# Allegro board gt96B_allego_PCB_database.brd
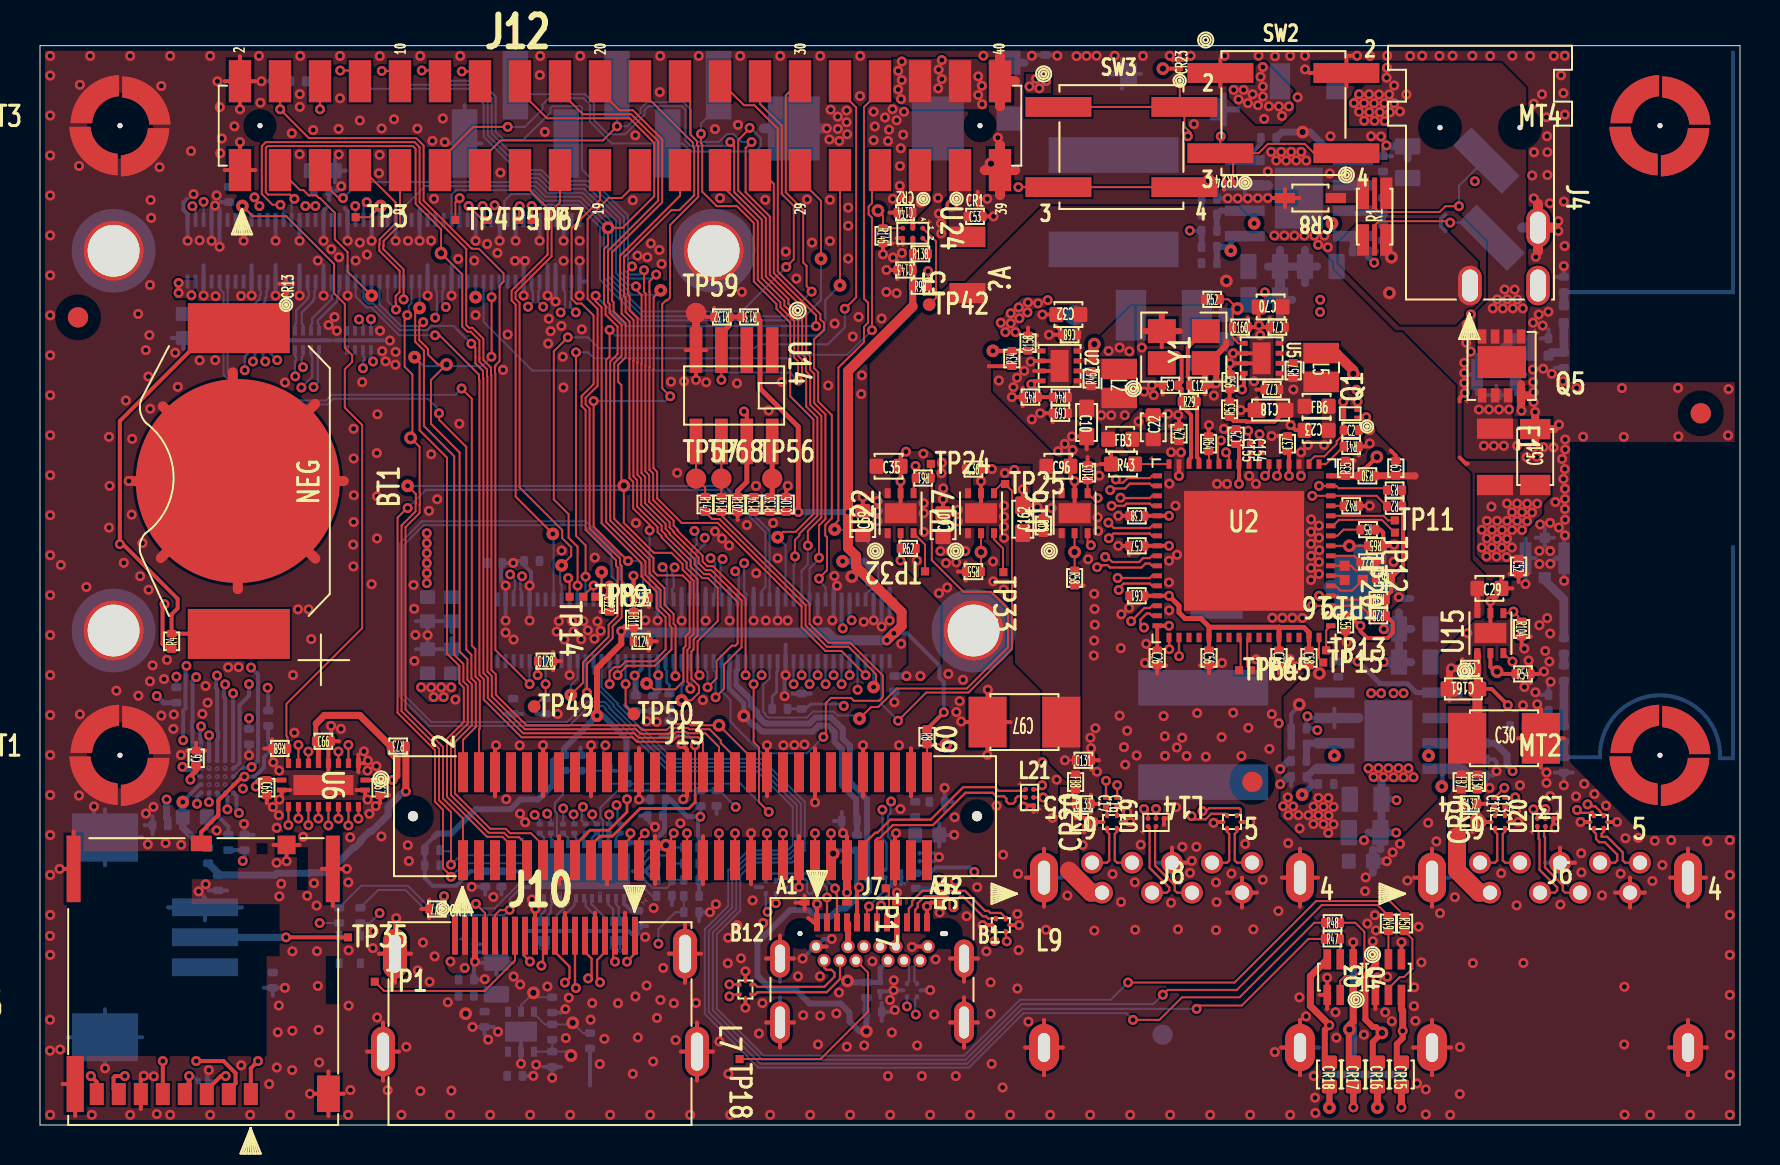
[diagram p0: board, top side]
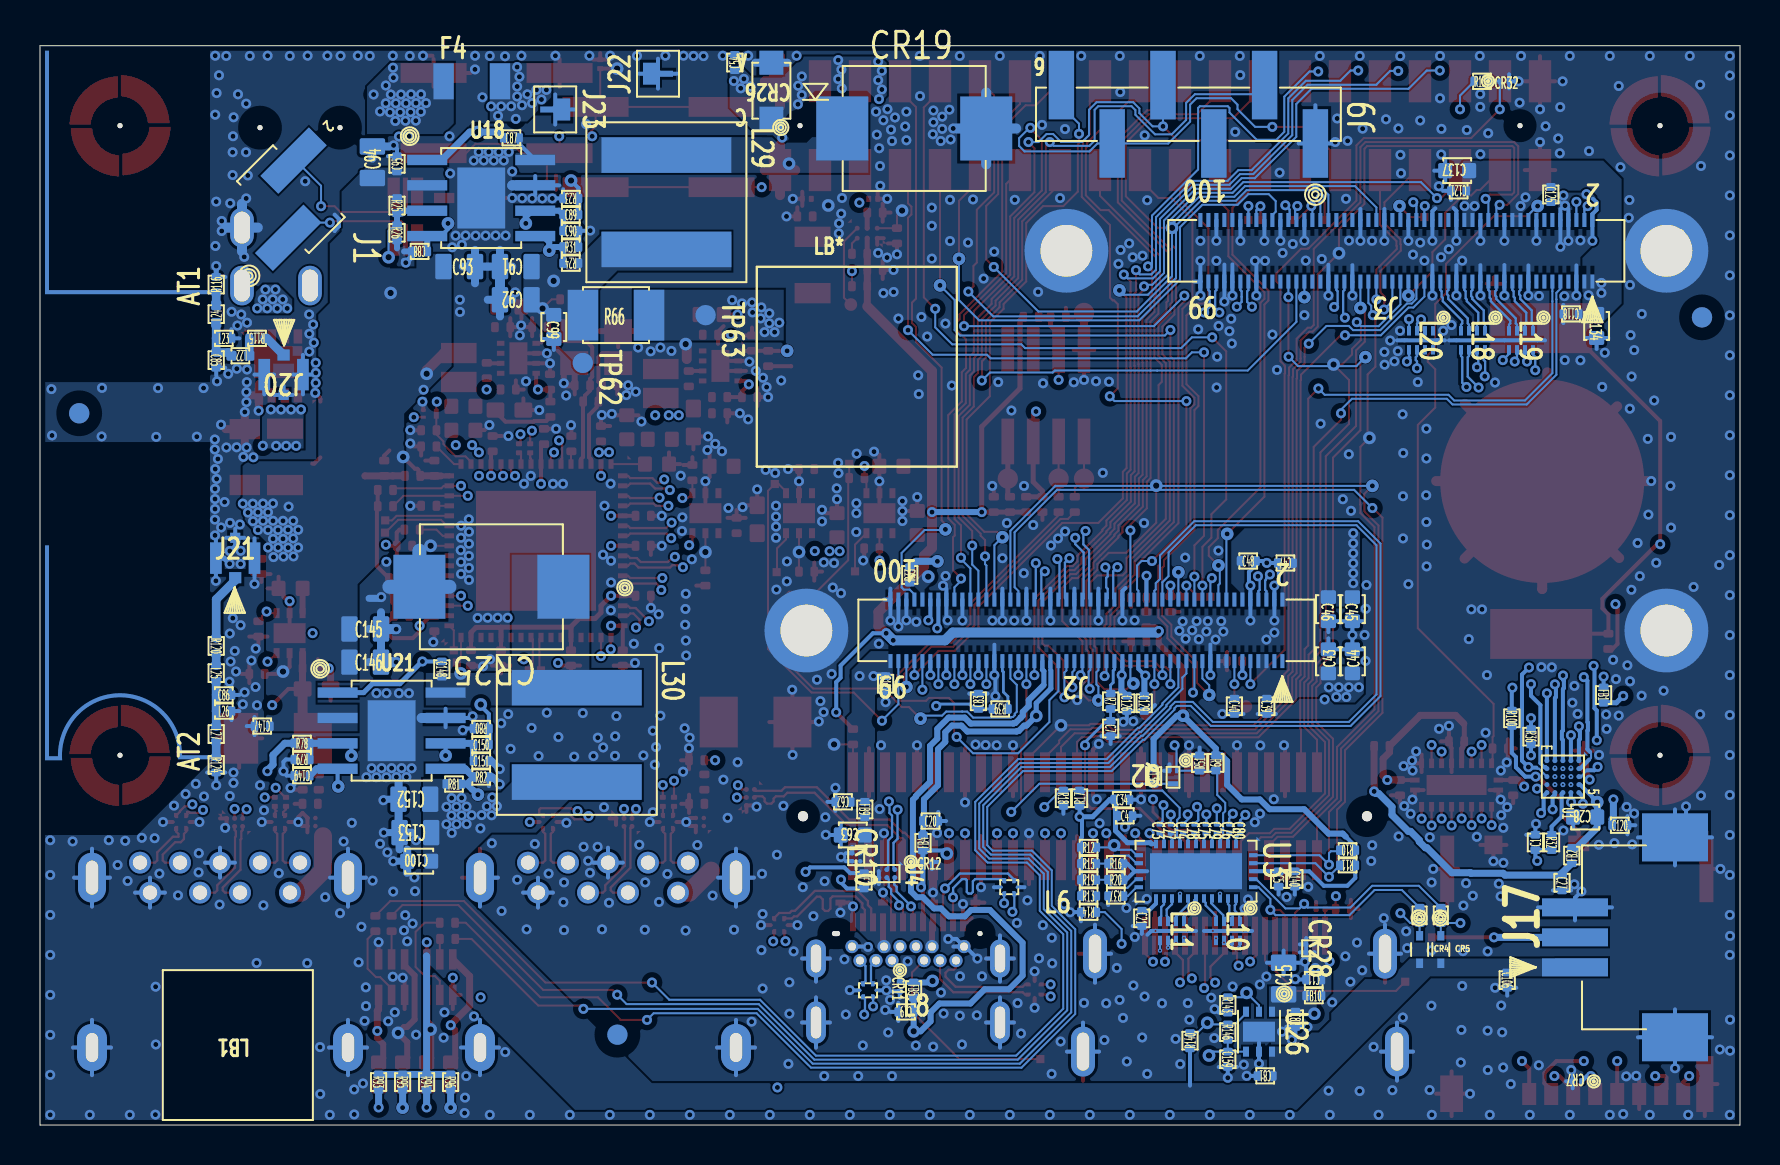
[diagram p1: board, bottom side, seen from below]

Outline 85 x 54 mm; copper layers: TOP, L2, L3, L4, L5, BOTTOM. Coordinates in mm from the lower left corner of the outline.
Outline path: 0,54 85,54 85,0 0,0 0,54

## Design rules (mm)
net group HUB1_USB2_1_D: nets HUB1_USB2_1_DN HUB1_USB2_1_DP
net group HUB1_USB3_1_RX_D: nets HUB1_USB3_1_RX_DN HUB1_USB3_1_RX_DP
net group HUB1_USB3_1_TX_D: nets HUB1_USB3_1_TX_DN HUB1_USB3_1_TX_DP
net group HUB1_USB3_1_TX_R_D: nets HUB1_USB3_1_TX_DN_C HUB1_USB3_1_TX_DP_C
net group HUB2_USB2_1_D: nets HUB2_USB2_1_DN HUB2_USB2_1_DP
net group HUB2_USB3_1_RX_D: nets HUB2_USB3_1_RX_DN HUB2_USB3_1_RX_DP
net group HUB2_USB3_1_TX_D: nets HUB2_USB3_1_TX_DN HUB2_USB3_1_TX_DP
net group HUB2_USB3_1_TX_R_D: nets HUB2_USB3_1_TX_DN_C HUB3_USB3_1_TX_DP_C
net group HUB3_USB2_1_CONN_D: nets HUB3_USB2_1_CONN_DN HUB3_USB2_1_CONN_DP
net group HUB3_USB2_1_D: nets HUB3_USB2_1_DN HUB3_USB2_1_DP
net group MDSI_A_DATA_3_CONN_D: nets MDSI_A_DATA_3_CONN_DN MDSI_A_DATA_3_CONN_DP
net group MDSI_A_DATA_3_D: nets MDSI_A_DATA_3_DN MDSI_A_DATA_3_DP
net group PCIE1_CLK_D: nets PCIE1_CLK_DN PCIE1_CLK_DP
net group USB2_0_D: nets USB2_0_DN USB2_0_DP
net group USB2_1_D: nets USB2_1_DN USB2_1_DP
net group USB3_0_MUX1_RX_D: nets USB3_0_MUX1_RX_DN USB3_0_MUX1_RX_DP
net group USB3_0_MUX1_TX_D: nets USB3_0_MUX1_TX_DN USB3_0_MUX1_TX_DP
net group USB3_0_MUX2_RX_D: nets USB3_0_MUX2_RX_DN USB3_0_MUX2_RX_DP
net group USB3_0_MUX2_TX_D: nets USB3_0_MUX2_TX_DN USB3_0_MUX2_TX_DP
net group USB3_0_RX_D: nets USB3_0_RX_DN USB3_0_RX_DP
net group USB3_0_TX_D: nets USB3_0_TX_DN USB3_0_TX_DP
net group USB3_1_RX_D: nets USB3_1_RX_DN USB3_1_RX_DP
net group USB3_1_RX_R: nets USB3_1_RX_DN_C USB3_1_RX_DP_C
net group USB3_1_TX_D: nets USB3_1_TX_DN USB3_1_TX_DP
net group USBA_1_USB2_1_D: nets USBA_1_USB2_1_DN USBA_1_USB2_1_DP
net group USBA_1_USB3_1_RX_D: nets USBA_1_USB3_1_RX_DN USBA_1_USB3_1_RX_DP
net group USBA_1_USB3_1_TX_D: nets USBA_1_USB3_1_TX_DN USBA_1_USB3_1_TX_DP
net group USBA_2_USB2_1_D: nets USBA_2_USB2_1_DN USBA_2_USB2_1_DP
net group USBA_2_USB3_1_RX_D: nets USBA_2_USB3_1_RX_DN USBA_2_USB3_1_RX_DP
net group USBA_2_USB3_1_TX_D: nets USBA_2_USB3_1_TX_DN USBA_2_USB3_1_TX_DP
net group USBC_USB2_0_D: nets USBC_USB2_0_DN USBC_USB2_0_DP
net group USBC_USB3_0_MUX1_RX_D: nets USBC_USB3_0_MUX1_RX_DN USBC_USB3_0_MUX1_RX_DP
net group USBC_USB3_0_MUX1_TX_D: nets USBC_USB3_0_MUX1_TX_DN USBC_USB3_0_MUX1_TX_DP
net group USBC_USB3_0_MUX2_RX_D: nets USBC_USB3_0_MUX2_RX_DN USBC_USB3_0_MUX2_RX_DP
net group USBC_USB3_0_MUX2_TX_D: nets USBC_USB3_0_MUX2_TX_DN USBC_USB3_0_MUX2_TX_DP
net group HDMI: nets HDMI_CLK_DN HDMI_CLK_DP HDMI_TX_0_DN HDMI_TX_0_DP HDMI_TX_1_DN HDMI_TX_1_DP HDMI_TX_2_DN HDMI_TX_2_DP
net group HDMI_C: nets HDMI_CLK_C_DN HDMI_CLK_C_DP HDMI_TX_0_C_DN HDMI_TX_0_C_DP HDMI_TX_1_C_DN HDMI_TX_1_C_DP HDMI_TX_2_C_DN HDMI_TX_2_C_DP
net group HDMI_CONN: nets HDMI_CLK_CONN_DN HDMI_CLK_CONN_DP HDMI_DAT0_CONN_DN HDMI_DAT0_CONN_DP HDMI_DAT1_CONN_DN HDMI_DAT1_CONN_DP HDMI_DAT2_CONN_DN HDMI_DAT2_CONN_DP
net group HDMI_OB: nets HDMI_OB_CLK_DN HDMI_OB_CLK_DP HDMI_OB_DAT0_DN HDMI_OB_DAT0_DP HDMI_OB_DAT1_DN HDMI_OB_DAT1_DP HDMI_OB_DAT2_DN HDMI_OB_DAT2_DP
net group MDSI_A: nets MDSI_A_CLK_DN MDSI_A_CLK_DP MDSI_A_DATA_0_DN MDSI_A_DATA_0_DP MDSI_A_DATA_1_DN MDSI_A_DATA_1_DP MDSI_A_DATA_2_DN MDSI_A_DATA_2_DP
net group MDSI_A_CONN: nets MDSI_A_CLK_CONN_DN MDSI_A_CLK_CONN_DP MDSI_A_DATA_0_CONN_DN MDSI_A_DATA_0_CONN_DP MDSI_A_DATA_1_CONN_DN MDSI_A_DATA_1_CONN_DP MDSI_A_DATA_2_CONN_DN MDSI_A_DATA_2_CONN_DP
net group SD_CARD: nets +V1P8V_MICROSD +V3P3V_MICROSD +VLDO_SDCARD
net group SDCARD: nets SDCARD_CD_N SDCARD_CD_N_CONN SDCARD_CLK SDCARD_CLK_CONN SDCARD_CLK_CONN_R SDCARD_CMD SDCARD_CMD_CONN SDCARD_D0 SDCARD_D0_CONN SDCARD_D1 SDCARD_D1_CONN SDCARD_D2 SDCARD_D2_CONN SDCARD_D3 SDCARD_D3_CONN SDCARD_LVL_CLK_FB SDCARD_LVL_CMD_DIR SDCARD_LVL_DAT_DIR SDCARD_LVL_SEL SDCARD_PWR_DOWN_N
net group WIFI_ANT: nets RF_ANT_WIFI_A RF_ANT_WIFI_B_BT RF_CONN_WIFI_A RF_CONN_WIFI_B_BT RF_MATCH_WIFI_A RF_MATCH_WIFI_A_L RF_MATCH_WIFI_B_BT RF_MATCH_WIFI_B_BT_L

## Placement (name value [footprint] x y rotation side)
AT1  -  [TEST_SP_C10SM13]  76.19 41.67 0 bottom
AT2  -  [TEST_SP_C10SM13]  76.19 18.39 0 bottom
BT1  -  [BATT_HLDR_3P_13P5X9P5MM]  9.94 24.57 90 top
C1  47PF  [SMC0402]  10.23 13.76 0 bottom
C2  1UF  [SMC0402]  65.18 34.76 90 top
C3  22PF  [SMC0402]  56.9 37.01 270 top
C4  1UF  [SMC0402]  31.14 15.47 90 bottom
C5  1UF  [SMC0402]  23.07 12.69 180 bottom
C6  1UF  [SMC0402]  7.81 17.97 180 top
C7  33PF  [SMC0402]  31.47 20.22 180 bottom
C9  0.1UF  [SMC0402]  67.79 32.48 180 top
C10  22UF  [SMC0603_67X35_42H]  52.33 35.85 0 top
C11  22PF  [SMC0402]  20.93 7.28 270 bottom
C12  22PF  [SMC0402]  57.5 37.01 90 top
C13  0.1UF  [SMC0201]  73.26 16.4 0 top
C14  0.1UF  [SMC0201]  72.7 16.4 0 top
C15  22UF  [SMC0805_1P45H]  22.82 6.54 0 bottom
C16  0.1UF  [SMC0201]  53.86 16.4 0 top
C17  0.1UF  [SMC0201]  53.3 16.4 0 top
C18  22UF  [SMC0603_67X35_42H]  62.23 35.77 270 top
C19  220PF  [SMC0402]  41.32 5.66 270 bottom
C20  220PF  [SMC0402]  40.85 15.21 90 bottom
C21  0.1UF  [SMC0402]  29.91 10.72 180 bottom
C22  10UF  [SMC0603]  55.66 34.31 180 top
C23  10UF  [SMC0603]  64.43 34.76 270 top
C24  0.1UF  [SMC0402]  56.95 34.21 180 top
C25  0.1UF  [SMC0402]  59.8 34.07 180 top
C26  0.1UF  [SMC0402]  55.86 23.75 0 top
C27  1UF  [SMC0402]  8.9 12.5 180 bottom
C28  10UF  [SMC0603]  7.14 15.41 270 bottom
C29  10UF  [SMC0603]  71.87 26.85 90 top
C30  100UF  [SMC1210]  71.36 19.35 90 top
C31  0.1UF  [SMC0402]  71.87 22.85 270 top
C32  10UF  [SMC0603]  52.02 40.55 270 top
C33  0.1UF  [SMC0402]  61.95 23.75 0 top
C34  0.1UF  [SMC0402]  31.29 16.28 90 bottom
C35  10UF  [SMC0603]  41.83 32.96 90 top
C36  2.2UF  [SMC0402]  46.29 32.82 90 top
C37  0.1UF  [SMC0402]  62.37 33.71 180 top
C38  0.1UF  [SMC0402]  55.22 30.48 270 top
C39  0.1UF  [SMC0402]  23.66 21.33 180 bottom
C40  0.1UF  [SMC0402]  25.28 21.33 180 bottom
C43  10UF  [SMC0603]  20.58 22.6 0 bottom
C44  10UF  [SMC0603]  19.38 22.6 0 bottom
C45  10UF  [SMC0603]  19.38 26.41 180 bottom
C46  10UF  [SMC0603]  20.58 26.41 180 bottom
C47  0.1UF  [SMC0402]  22.35 28.12 270 bottom
C48  0.1UF  [SMC0402]  24.97 28.22 90 bottom
C51  10UF  [SMC1206_1P8W_1P8H]  74.76 33.42 180 top
C52  0.1UF  [SMC0402]  73.93 28.33 0 top
C53  0.1UF  [SMC0402]  46.37 45.46 90 top
C54  0.1UF  [SMC0402]  50.26 52.78 0 bottom
C55  0.1UF  [SMC0402]  65.28 25.47 0 top
C56  0.1UF  [SMC0402]  58.45 23.75 0 top
C57  0.1UF  [SMC0402]  55.22 28.98 270 top
C58  0.1UF  [SMC0402]  63.45 23.75 0 top
C59  10UF  [SMC0603]  41.14 29.52 180 top
C60  10UF  [SMC0603]  45.15 29.41 180 top
C61  0.1UF  [SMC0402]  55.22 26.48 270 top
C62  220PF  [SMC0402]  44.47 16.17 270 bottom
C63  10UF  [SMC0603]  43.76 14.51 270 bottom
C65  2.2UF  [SMC0402]  11.34 17.26 0 top
C66  2.2UF  [SMC0402]  13.79 19.2 90 top
C67  2.2UF  [SMC0402]  17 17.26 0 top
C68  1UF  [SMC0402]  51.86 39.54 270 top
C69  1UF  [SMC0402]  51.4 35.61 270 top
C70  10UF  [SMC0603]  62.13 40.93 270 top
C71  1UF  [SMC0402]  62.25 39.92 270 top
C72  1UF  [SMC0402]  61.97 36.8 270 top
C73  0.1UF  [SMC0201]  29.02 15.06 180 bottom
C74  0.1UF  [SMC0201]  27.84 15.06 180 bottom
C75  0.1UF  [SMC0201]  26.72 15.06 180 bottom
C76  0.1UF  [SMC0201]  25.54 15.06 180 bottom
C77  0.1UF  [SMC0201]  28.46 15.06 180 bottom
C78  0.1UF  [SMC0201]  27.28 15.06 180 bottom
C79  0.1UF  [SMC0201]  26.16 15.06 180 bottom
C80  0.1UF  [SMC0201]  24.98 15.06 180 bottom
C81  0.1UF  [SMC0402]  23.36 2.46 270 bottom
C82  0.1UF  [SMC0402]  22.23 5.67 180 bottom
C83  33PF  [SMC0402]  38.08 20.82 0 bottom
C85  0.4PF  [SMC0402]  76.19 38.65 180 bottom
C86  0.3PF  [SMC0402]  76.19 21.52 90 bottom
C87  0.1UF  [SMC0402]  61.81 49.39 90 bottom
C88  10NF  [SMC0402]  65.64 43.71 270 bottom
C89  2200PF  [SMC0402]  58.84 45.55 90 bottom
C90  22PF  [SMC0402]  58.84 44.74 90 bottom
C91  47UF  [SMC0805_1P45H]  60.42 42.95 270 bottom
C92  47UF  [SMC0805_1P45H]  60.42 41.29 270 bottom
C93  4.7UF  [SMC0805_1P4H]  64.83 42.95 90 bottom
C94  4.7UF  [SMC0805_1P4H]  68.38 47.38 0 bottom
C95  0.01UF  [SMC0402]  67.15 47.71 0 bottom
C96  10UF  [SMC0603]  50.32 32.96 90 top
C97  100UF  [SMC1210]  51.06 20.16 270 top
C98  0.1UF  [SMC0402]  50.17 29.61 180 top
C99  10UF  [SMC0603]  59.31 40.53 180 bottom
C100  10UF  [SMC0603]  65.44 13.2 270 bottom
C105  0.1UF  [SMC0402]  37.31 30.67 180 top
C106  0.1UF  [SMC0402]  11.64 7.63 180 bottom
C118  0.1UF  [SMC0402]  8.07 40.58 270 bottom
C120  1UF  [SMC0402]  6.39 15 90 bottom
C121  0.1UF  [SMC0402]  13.69 46.74 270 bottom
C122  0.1UF  [SMC0402]  28.48 26.44 0 top
C123  0.1UF  [SMC0402]  29.68 26.38 90 top
C124  47PF  [SMC0402]  29.68 24.2 90 top
C125  0.1UF  [SMC0402]  9.46 46.94 180 bottom
C126  0.1UF  [SMC0402]  30.66 21.48 180 bottom
C127  0.1UF  [SMC0402]  42.72 22.46 180 bottom
C128  0.1UF  [SMC0402]  24.89 23.21 90 top
C129  0.1UF  [SMC0402]  29.79 21.48 180 bottom
C130  0.1UF  [SMC0402]  71.87 17.54 0 top
C131  0.1UF  [SMC0402]  51.79 18.25 90 top
C132  47PF  [SMC0402]  71.11 16.07 90 top
C133  47PF  [SMC0402]  51.78 16.07 90 top
C134  10UF  [SMC0603]  7.17 40.58 180 bottom
C137  10UF  [SMC0603]  13.54 47.75 270 bottom
C140  0.1UF  [SMC0402]  22.26 12.69 180 bottom
C143  2.2UF  [SMC0402]  43.63 42.78 270 top
C144  0.1UF  [SMC0402]  43.63 45.65 270 top
C145  4.7UF  [SMC0805_1P4H]  69.53 24.82 90 bottom
C146  4.7UF  [SMC0805_1P4H]  69.53 23.16 90 bottom
C147  0.1UF  [SMC0402]  73.51 19.96 270 bottom
C148  0.1UF  [SMC0402]  64.91 23.19 180 bottom
C149  4.7NF  [SMC0402]  71.52 17.48 270 bottom
C150  2200PF  [SMC0402]  63.32 19.03 90 bottom
C151  22PF  [SMC0402]  63.32 18.22 90 bottom
C152  47UF  [SMC0805_1P45H]  65.49 16.3 270 bottom
C153  47UF  [SMC0805_1P45H]  65.44 14.63 270 bottom
C154  0.1UF  [SMC0201]  61.05 34.09 0 top
C155  0.1UF  [SMC0201]  60.49 34.09 0 top
C158  1UF  [SMC0402]  49.4 38.74 180 top
C159  0.1UF  [SMC0402]  25.61 3.67 180 bottom
C160  1UF  [SMC0402]  59.63 39.92 90 top
C161  22UF  [SMC0603_67X35_42H]  71.87 21.82 270 top
C162  22UF  [SMC0603_67X35_42H]  49.14 29.61 180 top
CR1  -  [SMCR0201]  46.43 46.34 90 top
CR2  -  [SMCR0201]  43.57 46.34 270 top
CR4  DB2S31000L  [SMCR_0P85X1P25_P65H]  16.02 8.78 180 bottom
CR5  DB2S31000L  [SMCR_0P85X1P25_P65H]  14.96 8.78 180 bottom
CR7  -  [SMCR0201]  7.91 2.19 270 bottom
CR8  -  [SOD323]  64.79 46.38 270 top
CR9  -  [BGA4_FLIPCHIP]  71.23 14.96 90 top
CR10  -  [BGA4_FLIPCHIP]  43.99 13.6 270 bottom
CR11  -  [SMCR0201]  42.01 7.14 180 bottom
CR12  -  [SMCR0201]  40.85 13.16 90 bottom
CR13  -  [SMCR0201]  12.31 41.64 180 top
CR14  -  [SMCR0201]  20.75 10.81 90 top
CR15  -  [SMLED0603]  68.07 3.13 0 top
CR16  -  [SMLED0603]  66.87 3.13 0 top
CR17  -  [SMLED0603]  65.67 3.13 0 top
CR18  -  [SMLED0603]  64.47 3.13 0 top
CR19  -  [DO214AB]  41.29 49.86 180 bottom
CR20  -  [BGA4_FLIPCHIP]  51.81 14.96 90 top
CR23  -  [SMCR0201]  56.99 52.85 180 top
CR24  -  [SMCR0201]  59.66 47.15 270 top
CR25  -  [DO214AB]  62.43 26.93 0 bottom
CR26  -  [SOD123W]  48.43 51.75 0 bottom
CR28  -  [BGA4_FLIPCHIP]  21.29 9.04 270 bottom
CR32  -  [SMCR0201]  12 52.22 90 bottom
F1  -  [SMFUSE1206_34H]  72.75 34.84 270 top
F2  -  [SMFUSE0402_P432H]  43.8 12.6 180 bottom
F4  -  [SMFUSE1206_34H]  64.82 52.22 180 bottom
F5  -  [SMFUSE1206_39H]  46.37 41.62 90 top
FB1  -  [SMF0402]  6.82 21.89 180 bottom
FB2  -  [SMF0402]  8.41 13.1 0 bottom
FB3  -  [SMF0603]  53.41 34.31 90 top
FB4  -  [SMF0402]  40.85 13.74 0 bottom
FB5  -  [SMF0402]  41.32 7.13 180 bottom
FB6  -  [SMF0603]  63.23 35.96 90 top
FB7  -  [SMF0402]  71.06 17.54 0 top
FB8  -  [SMF0402]  51.78 17.54 0 top
FB9  -  [SMF0402]  43.76 16.17 180 bottom
FB10  -  [SMF0402]  21.69 6.47 90 bottom
FB11  -  [SMF0402]  29.68 25.67 0 top
J1  -  [A79471-001]  72.59 44.39 315 bottom
J2  -  [2X50_P4MM_1P6H_BTB_RCPT_DF40C]  22.88 23.21 0 bottom
J3  -  [2X50_P4MM_1P6H_BTB_RCPT_DF40C]  7.38 42.2 0 bottom
J4  -  [DC_PWR_JACK_1P65X5P15MM_RA_TH]  71.5 42 270 top
J5  -  [CON8_1P1MM_SD503398_MOLEX]  10.54 1.55 180 top
J6  -  [CON9_USB3_RA_TH_6P86H]  76 12.13 0 top
J7  -  [CON24_USB_C_HYBRID_10P15X11P35]  41.6 9.58 0 top
J8  -  [CON9_USB3_RA_TH_6P86H]  56.6 12.13 0 top
J9  -  [1X6_P100IN_SM_HDR]  27.58 50.57 0 bottom
J10  -  [CON19_P5MM_HDMI_MALE_RA_SM_6P3H]  25 3.67 0 top
J12  -  [2X20_2MM_3P98X40_RCPT_REV]  29 50 0 top
J13  -  [2X30_P8MM_BTB_RCPT_VT_4P0H]  32.75 15.45 0 top
J15  -  [PEM_NUT_2P31_3P66MM_1P5H]  3.68 24.74 180 bottom
J16  -  [PEM_NUT_2P31_3P66MM_1P5H]  46.68 24.74 180 bottom
J17  -  [CON3_1P5MM_4P9H_SM_MINI_CT]  8.25 7.89 90 bottom
J18  -  [PEM_NUT_2P31_3P66MM_1P5H]  33.68 43.74 180 bottom
J19  -  [PEM_NUT_2P31_3P66MM_1P5H]  3.68 43.74 180 bottom
J20  -  [CONN_COAX_SMT_2X2]  72.82 37.55 0 bottom
J21  -  [CONN_COAX_SMT_2X2]  75.24 28.36 180 bottom
J22  -  [CABLE_HOLDER_SV08M]  54.1 52.6 90 bottom
J23  -  [CABLE_HOLDER_SV08M]  59.24 50.81 270 bottom
L2  1.0UH  [SML0806]  53.96 37.1 0 top
L3  35OHM  [SML_6P_0P65X0P85]  78.19 14.84 180 top
L4  35OHM  [SML_6P_0P65X0P85]  73.25 14.84 180 top
L5  1.0UH  [SML0806]  64.06 37.9 0 top
L6  35OHM  [SML_6P_0P65X0P85]  36.8 12.22 180 bottom
L7  35OHM  [SML_6P_0P65X0P85]  35.59 7.04 270 top
L8  35OHM  [SML_6P_0P65X0P85]  43.85 7.06 180 bottom
L9  35OHM  [SML_6P_0P65X0P85]  47.78 10.32 0 top
L10  90OHM  [LCC10_P4MM_1608]  25 10.19 270 bottom
L11  90OHM  [LCC10_P4MM_1608]  27.8 10.19 270 bottom
L14  35OHM  [SML_6P_0P65X0P85]  59.85 14.84 180 top
L15  35OHM  [SML_6P_0P65X0P85]  53.85 14.84 180 top
L18  90OHM  [LCC10_P4MM_1608]  12.75 39.73 270 bottom
L19  90OHM  [LCC10_P4MM_1608]  10.35 39.73 270 bottom
L20  90OHM  [LCC10_P4MM_1608]  15.35 39.73 270 bottom
L21  -  [BGA5_P4MM_1P27XP86MM]  49.48 16.39 0 top
L22  1.3NH  [SML_40X24]  74.54 38.49 270 bottom
L23  10NH  [SML0402]  76.19 39.36 90 bottom
L24  1.3NH  [SML_40X24]  76.19 40.13 0 bottom
L25  2.2NH  [SML0402]  76.19 22.99 180 bottom
L26  2.7NH  [SML0402]  76.19 20.71 90 bottom
L27  1.0NH  [SML0402]  76.19 19.94 180 bottom
L29  4.7UH  [SML_SQ7P5_3P1H]  53.68 46.17 270 bottom
L30  4.7UH  [SML_SQ7P5_3P1H]  58.16 19.52 270 bottom
LB1  -  [2D_ID_TARGET_7P5X7P5MM_NOSM]  75.11 4 0 bottom
LB*  -  [unnamed#3]  44.16 37.94 180 bottom
MT1  -  [MTG_C10N98_197PAD]  4 18.5 0 top
MT2  -  [MTG_C10N98_197PAD]  81 18.5 0 top
MT3  -  [MTG_C10N98_197PAD]  4 50 0 top
MT4  -  [MTG_C10N98_197PAD]  81 50 0 top
NOREF  -  []  181.31 126.12 0 top
NOREF#2  -  []  101.47 127.25 0 top
NOREF#3  -  []  0 0 0 top
NOREF#4  -  []  -9.65 128.32 0 top
NOREF#5  -  []  166.61 -8.79 0 top
NOREF#6  -  []  4 18.5 0 top
NOREF#7  -  []  0 54 0 top
NOREF#8  -  []  3.55 1.24 90 top
NOREF#9  -  []  4 18.5 0 top
NOREF#10  -  []  0 4.79 0 top
NOREF#11  -  []  0 54 0 top
NOREF#12  -  []  186.77 119.42 0 top
NOREF#13  -  []  90.22 58.59 0 top
NOREF#14  -  []  -10.16 -9.65 0 top
NOREF#15  -  []  -6.36 119.02 0 top
NOREF#16  -  [unnamed#2]  83.04 35.61 0 top
NOREF#17  -  []  1.48 126.04 0 top
NOREF#18  -  []  113.49 120.69 0 top
NOREF#19  -  []  0 13.99 90 top
NOREF#20  -  []  15.58 127.08 0 top
NOREF#21  -  []  1.07 -7.66 0 top
NOREF#22  -  []  4 18.5 0 top
NOREF#23  -  []  128.43 -6.5 0 top
NOREF#24  -  []  189.85 128.32 0 top
NOREF#25  -  []  182.78 -6.79 0 top
NOREF#26  -  []  138.23 124.95 0 top
NOREF#27  -  []  186.77 -1.22 0 top
NOREF#28  -  []  72.54 -8.79 0 top
NOREF#29  -  []  15.58 128.32 0 top
NOREF#30  -  []  8.69 37.32 0 top
NOREF#31  -  []  4 18.5 0 top
NOREF#32  -  [unnamed#2]  60.62 17.17 0 top
NOREF#33  -  []  8.69 22.02 0 top
NOREF#34  -  []  85 0 0 top
NOREF#35  -  []  190.32 127.81 0 top
NOREF#36  -  [unnamed#2]  1.9 40.41 0 top
NOREF#37  -  []  -7.63 119.46 0 top
NOREF#38  -  []  85 0 90 top
NOREF#39  -  []  176.16 99.66 0 top
NOREF#40  -  []  2.1 14.96 90 top
NOREF#41  -  []  0 0 0 top
NOREF#42  -  []  10.57 126.53 0 top
NOREF#43  -  []  -2.48 79.94 0 top
NOREF#44  -  []  14.75 2.89 90 top
NOREF#45  -  []  81 99.66 0 top
NOREF#46  -  []  29.38 33.73 0 top
NOREF#47  -  []  9.89 32.22 90 top
NOREF#48  -  []  99.16 18.5 0 top
NOREF#49  -  []  0 4.79 90 top
NOREF#50  -  []  81 99.66 0 top
NOREF#51  -  []  -9.65 -10.16 0 top
NOREF#52  -  []  -4.61 -4.05 0 top
NOREF#53  -  []  8.69 22.02 90 top
NOREF#54  -  []  18.63 120.37 0 top
NOREF#55  -  [unnamed#2]  1.9 40.41 180 bottom
NOREF#56  -  [unnamed#4]  50.53 21.52 180 bottom
NOREF#57  -  []  24.02 34.75 180 bottom
NOREF#58  -  [unnamed#4]  15.45 22.54 180 bottom
NOREF#59  -  [unnamed#2]  83.04 35.61 180 bottom
NOREF#60  -  [unnamed#2]  56.13 4.52 180 bottom
NOREF#61  -  [unnamed#3]  9.37 26.81 180 bottom
Q1  -  [SM_3P_0P6X1P0]  65.83 35.41 90 top
Q2  -  [SM_3P_0P6X1P0]  28.18 17.73 0 bottom
Q3  -  [SOT363]  66.77 6.51 90 top
Q4  -  [SOT363]  65.66 8.29 270 top
Q5  -  [WPAK8_3P3MMSQ_P8H]  72.1 36.51 0 top
R1  10milliOHM  [SMR1206_SNS_B]  66.73 44.05 180 top
R2  10K  [SMR0402]  68.11 30.96 270 top
R3  10K  [SMR0402]  68.11 31.77 270 top
R4  1.1K  [SMR0402]  6.58 23.82 180 top
R5  4.7K  [SMR0402]  66.78 29.79 270 top
R7  0  [SMR0402]  31.47 21.58 180 bottom
R8  100K  [SMR0402]  44.35 19.81 0 top
R9  10K  [SMR0402]  26.21 18.5 180 bottom
R10  2.7K  [SMR0402_16H]  19.62 13.75 270 bottom
R11  2.7K  [SMR0402_16H]  19.62 12.99 270 bottom
R12  10K  [SMR0402]  32.95 13.89 90 bottom
R13  10K  [SMR0402]  32.95 11.46 90 bottom
R14  10K  [SMR0402]  32.19 10.65 270 bottom
R15  10K  [SMR0402]  32.95 13.08 90 bottom
R16  10K  [SMR0402]  31.59 13.08 90 bottom
R17  10K  [SMR0402]  33.02 15.97 0 bottom
R18  10K  [SMR0402]  33.83 16.73 180 bottom
R19  10K  [SMR0402]  32.95 12.27 90 bottom
R20  10K  [SMR0402]  31.59 12.27 90 bottom
R21  2.7K  [SMR0402_16H]  14.96 10.49 0 bottom
R22  2.7K  [SMR0402_16H]  16.02 10.49 0 bottom
R23  37.4K  [SMR0402]  58.08 46.36 270 bottom
R24  10K  [SMR0402]  58.08 43.12 270 bottom
R25  649K  [SMR0402]  67.15 46.38 180 bottom
R26  130K  [SMR0402]  67.15 45.02 180 bottom
R27  4.7K  [SMR0402]  66.78 28.17 270 top
R28  4.7K  [SMR0402]  67.3 25.48 270 top
R29  1M  [SMR0402]  57.08 36.2 90 top
R30  90.9K  [SMR0402]  66.75 32.48 270 top
R31  1.87K  [SMR0402]  58.84 43.93 90 bottom
R32  0  [SMR0402]  9.42 14.52 180 bottom
R33  0  [SMR0402]  41.51 27.14 0 bottom
R34  4.7K  [SMR0402]  48.59 37.97 180 top
R35  10K  [SMR0402]  65.28 32.48 180 top
R36  100K  [SMR0402]  10.45 19.81 180 bottom
R37  4.99K  [SMR0402]  30.83 11.46 270 bottom
R38  4.7K  [SMR0402]  67.3 26.29 270 top
R39  0  [SMR0402]  36.61 20.82 270 bottom
R41  4.7K  [SMR0402]  65.94 33.95 270 top
R42  4.7K  [SMR0402]  65.94 30.98 270 top
R43  9.53K  [SMR0603]  53.55 33.07 90 top
R44  237K  [SMR0402]  51.4 36.42 270 top
R45  37.4K  [SMR0402]  49.9 36.42 270 top
R46  100K  [SMR0402]  52.56 36.96 180 top
R47  1.1K  [SMR0402]  64.24 9.31 90 top
R48  1.1K  [SMR0402]  64.25 10.12 90 top
R49  1.1K  [SMR0402]  67.42 10.46 0 top
R50  1.1K  [SMR0402]  68.23 10.46 0 top
R51  100K  [SMR0402]  27.02 17.73 0 bottom
R52  0  [SMR0402]  58.23 41.31 90 top
R53  56.2K  [SMR0402]  59.48 35.43 180 top
R54  26.1K  [SMR0402]  73.77 22.57 90 top
R55  76.8K  [SMR0402]  47.05 27.69 270 top
R56  37.4K  [SMR0402]  59.5 37.56 0 top
R57  100K  [SMR0402]  62.66 37.37 180 top
R58  26.1K  [SMR0402]  51.73 27.75 0 top
R61  0  [SMR0402]  44.54 32.37 270 top
R62  26.1K  [SMR0402]  43.03 28.85 90 top
R63  4.7K  [SMR0402]  67.55 27.36 270 top
R64  0  [SMR0402]  58.43 34.47 0 top
R65  4.7K  [SMR0402]  67.16 28.98 270 top
R66  0  [SMR1210]  57.85 40.52 90 bottom
R68  100K  [SMR0402]  12.37 18.84 270 top
R73  0  [SMR0402]  18.29 18.96 270 top
R77  10K  [SMR0402]  20.22 10.81 270 top
R78  0  [SMR0402]  72.28 19.1 90 bottom
R79  10K  [SMR0402]  71.52 18.29 270 bottom
R80  37.4K  [SMR0402]  62.56 19.84 270 bottom
R81  10K  [SMR0402]  64.68 17.06 90 bottom
R82  1.87K  [SMR0402]  63.32 17.41 90 bottom
R93  560  [SMR0402]  68.07 2.53 180 bottom
R94  560  [SMR0402]  65.67 2.53 180 bottom
R95  560  [SMR0402]  66.87 2.53 180 bottom
R96  560  [SMR0402]  64.47 2.53 180 bottom
R98  100  [SMR0402]  43.64 41.97 90 top
R100  0  [SMR0402]  11.41 20.73 180 bottom
R102  10K  [SMR0402]  34.88 31.43 0 top
R103  4.7K  [SMR0402]  52.38 32.26 180 top
R104  4.7K  [SMR0402]  74.08 25.2 0 top
R115  0  [SMR0402]  73.77 39.36 270 bottom
R116  0  [SMR0402]  76.19 41.67 0 bottom
R120  0  [SMR0402]  76.19 24.35 180 bottom
R124  0  [SMR0402]  76.19 18.4 180 bottom
R131  10K  [SMR0402]  35.83 40.43 270 top
R132  10K  [SMR0402]  34.47 40.43 270 top
R133  0  [SMR0402]  36.5 30.67 180 top
R134  10K  [SMR0402]  35.69 30.67 180 top
R136  1.1K  [SMR0402]  29.32 17.84 180 bottom
R137  0  [SMR0402]  13.28 52.22 90 bottom
R138  0  [SMR0402]  43.64 43.59 90 top
R140  100K  [SMR0402]  27.5 3.84 0 bottom
R141  0  [SMR0402]  34.07 30.67 180 top
R142  0  [SMR0402]  33.26 31.43 0 top
R143  150K  [SMR0402]  25.61 6.39 180 bottom
R145  3.65K  [SMR0402]  42.15 44.87 0 top
R146  0  [SMR0402]  25.61 5.03 180 bottom
SW2  -  [672681-002]  59.02 52.64 0 top
SW3  -  [672681-002]  50.92 50.94 0 top
TP1  -  [TESTPAD_S16]  16.74 7.17 0 top
TP3  -  [TESTPAD_S16]  15.78 45.42 0 top
TP4  -  [TESTPAD_S16]  20.77 45.28 0 top
TP5  -  [TESTPAD_S16]  22.38 45.28 0 top
TP6  -  [TESTPAD_S16]  23.97 45.28 0 top
TP7  -  [TESTPAD_S16]  24.58 45.28 0 top
TP8  -  [TESTPAD_S16]  27.16 26.43 0 top
TP9  -  [TESTPAD_S16]  27.77 26.43 0 top
TP11  -  [TESTPAD_S16]  67.74 30.25 0 top
TP12  -  [TESTPAD_S16]  67.75 29.64 270 top
TP13  -  [TESTPAD_S16]  64.31 23.75 0 top
TP14  -  [TESTPAD_S16]  26.48 26.43 270 top
TP15  -  [TESTPAD_S16]  64.16 23.14 0 top
TP16  -  [TESTPAD_S20]  65.23 27.27 270 top
TP17  -  [TESTPAD_S16]  42.29 11.84 270 top
TP18  -  [TESTPAD_S16]  34.98 3.3 270 top
TP19  -  [TESTPAD_S20]  66.14 27.27 270 top
TP20  -  [TESTPAD_S20]  65.23 27.98 0 top
TP24  -  [TESTPAD_S16]  44.54 33.08 0 top
TP25  -  [TESTPAD_S16]  48.26 32.07 0 top
TP32  -  [TESTPAD_S16]  44.25 27.7 180 top
TP33  -  [TESTPAD_S16]  48.17 27.66 270 top
TP35  -  [TESTPAD_S16]  15.4 9.39 0 top
TP42  -  [TESTPAD_S16]  44.46 41.05 0 top
TP49  -  [TESTPAD_S16]  24.71 20.94 0 top
TP50  -  [TESTPAD_S16]  29.69 20.56 0 top
TP56  -  [TESTPAD_C40]  36.61 32.34 90 top
TP57  -  [TESTPAD_C40]  32.8 32.34 90 top
TP59  -  [TESTPAD_C40]  32.8 40.63 90 top
TP62  -  [TESTPAD_C40]  57.86 38.13 180 bottom
TP63  -  [TESTPAD_C40]  51.72 40.52 180 bottom
TP64  -  [TESTPAD_S16]  59.95 22.75 0 top
TP65  -  [TESTPAD_S16]  60.56 22.75 0 top
TP68  -  [TESTPAD_C40]  34.07 32.34 90 top
U1  -  [BGA25_P4MM_2P06SQ_P5H]  8.85 17.43 270 bottom
U2  -  [LCC64_P5MM_9SQ_EP6P0]  60.2 28.73 0 top
U3  -  [LCC32_P4MM_6X3_P8H]  27.2 12.7 270 bottom
U4  -  [BGA5_P4MM_1P27XP86MM]  42.66 12.58 270 bottom
U5  -  [LCC8_P5MM_2P1SQ_EP1P6XP9]  61.08 38.36 270 top
U6  -  [LCC20_P5MM_2P5X4P5_EP1X3]  14.17 17.01 270 top
U14  -  [SOI8_50IN_157X197]  36.61 39.23 270 top
U15  -  [LCC6_P65MM_2P1X2P1_EP1P0X1P6]  71.87 23.61 90 top
U16  -  [LCC6_P65MM_2P1X2P1_EP1P0X1P6]  51.08 29.61 90 top
U17  -  [LCC6_P65MM_2P1X2P1_EP1P0X1P6]  46.4 29.61 90 top
U18  -  [SOI8_1P27_5X4MM_EP2P4X3P05_1P7H]  62.94 46.38 180 bottom
U19  -  [BGA5_P4MM_1P27XP86MM]  55.8 15.14 90 top
U20  -  [BGA5_P4MM_1P27XP86MM]  75.27 15.14 90 top
U21  -  [SOI8_1P27_5X4MM_EP2P4X3P05_1P7H]  67.42 19.73 180 bottom
U22  -  [LCC6_P65MM_2P1X2P1_EP1P0X1P6]  42.38 29.61 90 top
U24  -  [CSP6_P5MM_1P55X1P05]  43.64 44.62 270 top
U26  -  [LCC6_P65MM_2P1X2P1_EP1P0X1P6]  23.4 5.67 270 bottom
U27  -  [LCC8_P5MM_2P1SQ_EP1P6XP9]  50.98 37.98 270 top
Y1  -  [SMY_4P_98X126_32H]  56.09 38.12 90 top

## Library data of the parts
AT1 AT2 = TESTPAD_CIR: part number: TESTPAD_CIR_SM13-C10,EMPTY
BT1 = BATT_HLDR_3P: part number: BATT_HLDR_3P_SM-CONN,MEMORY PROTECTION DEVICES,BK-916-TR,J30887-001
C1 C124 C132 C133 = CAP: part number: CAP_0402-47PF,5%,50V,COG,D17310-001
C2 C4-C6 C27 C68 C69 C71 C72 C120 C158 = CAP: part number: CAP_0402-1UF,10%,16V,X5R,A36096-111
C3 C12 = CAP: part number: CAP_0402-22PF,2%,50V,NPO,A36095-074
C7 C83 = CAP: part number: CAP_0402-33PF,10%,50V,EMPTY,J30783-001
C9 C31 C34 C39 C40 C47 C48 C53 C81 C82 C98 C106 C118 C121-C123 C125-C128 C130 C131 C144 C159 = CAP: part number: CAP_0402-0.1UF,10%,16V,X7R,A36096-030
C10 C18 = CAP_ALTSIZE: part number: CAP_ALTSIZE_0603-22UF,20%,10V,X5R,602433-105; room: PM_CHARGER
C11 C90 C151 = CAP: part number: CAP_0402-22PF,5%,50V,COG,A36095-030
C13 C14 C16 C17 C73-C80 C154 C155 = CAP: part number: CAP_0201-0.1UF,10%,6.3V,X5R,C83410-003
C15 = CAP: part number: CAP_0805-22UF,20%,25V,EMPTY,644066-120
C19 C20 = CAP: part number: CAP_0402-220PF,5%,50V,COG,A36095-045; room: NO_ROOM
C21 = CAP: part number: CAP_0402-0.1UF,10%,10V,X5R,A36096-043; room: NO_ROOM
C22 C23 C28 C29 C32 C35 C43-C46 C59 C60 C63 C70 C96 C99 C100 C134 C137 = CAP: part number: CAP_0603-10UF,20%,16V,X5R,602433-098
C24-C26 C33 C37 C38 C55-C58 C61 C105 C140 = CAP: part number: CAP_0402-0.1UF,10%,10V,X5R,A36096-043
C30 C97 = CAP: part number: CAP_1210-100UF,20%,10V,X5R,644066-093; room: USB
C36 C65-C67 C143 = CAP: part number: CAP_0402-2.2UF,20%,16V,X5R,A36096-149
C51 = CAP_ALTSIZE: part number: CAP_ALTSIZE_1206-10UF,20%,35V,X5R,H81071-001
C52 C54 C87 C129 C147 C148 = CAP: part number: CAP_0402-0.1UF,20%,50V,X5R,A36096-150
C62 = CAP: part number: CAP_0402-220PF,5%,50V,COG,A36095-045
C85 = CAP: part number: CAP_0402-0.4PF,+-0.05PF,50V,EMPTY,A64927-095
C86 = CAP: part number: CAP_0402-0.3PF,+-0.05PF,50V,HIQ,A36094-062
C88 = CAP: part number: CAP_0402-10NF,10%,25V,X7R,A36096-045
C89 C150 = CAP: part number: CAP_0402-2200PF,10%,50V,X7R,A36096-022
C91 C92 C152 C153 = CAP_ALTSIZE: part number: CAP_ALTSIZE_0805-47UF,20%,10V,X5R,644066-136
C93 C94 C145 C146 = CAP_ALTSIZE: part number: CAP_ALTSIZE_0805-4.7UF,10%,50V,X5R,644066-138
C95 = CAP: part number: CAP_0402-0.01UF,10%,50V,X7R,A36096-100
C149 = CAP: part number: CAP_0402-4.7NF,10%,50V,X7R,A36096-066
C160 = CAP: part number: CAP_0402-1UF,10%,16V,EMPTY,A36096-111
C161 C162 = CAP_ALTSIZE: part number: CAP_ALTSIZE_0603-22UF,20%,10V,X5R,602433-105; room: NO_ROOM
CR1 CR2 CR7 CR11-CR14 CR23 CR24 CR32 = DIO_ESD: part number: DIO_ESD_0201-ESDAVLC8,ESD,8.5V,15KV,DIO,G44940-001
CR4 CR5 = DIODE: part number: DIODE_0603-DB2S31000L,SHTKY,30V,200MA,DIO,G20461-001; room: HDMI_MISC
CR8 = PESD24VL1BA: part number: PESD24VL1BA_SOD323-PESD24VL1BA,ESD,24V,23KV,DIO,J43149-001
CR9 CR10 CR20 CR28 = DIOD_ESD_4P: part number: DIOD_ESD_4P_BGA4-LFTVS18-1F3,ESD,,,DIO,E87019-001
CR15-CR18 = LED: part number: LED_0603-GREEN,VERT,IF_80MA,PD_75MW,LED,H30760-001
CR19 CR25 = CDBC540_G: part number: CDBC540_G_SM-100V,5A,DIO,COMCHIP,CDBC540-G,J16948-001
CR26 = DIODE_ESD_2P: part number: DIODE_ESD_2P_SOD123W-PTVS24VS1UR,ESD,64V,30KV,EMPTY,J21027-001
F1 F4 = FUSE: part number: FUSE_1206-FUSE,6A,64V,BEL FUSE,0685F6000,J21088-001
F2 = FUSE: part number: FUSE_0402-FUSE,2A,32V,LITTLEFUSE,0435002.KRHF,C94311-018
F5 = FUSE: part number: FUSE_1206-FUSE,1A,6V,BEL FUSE,0ZCJ0100FF2E,J21088-002
FB1 FB2 = FERRITE: part number: FERRITE_SM-FB,120OHM,100MHZ,1.3A,A51464-017; room: STORAGE_REMV
FB3 FB6 = FERRITE: part number: FERRITE_SM-FB,220.0OHM,100MHZ,1.4A,D86941-001
FB4 FB5 FB7-FB11 = FERRITE: part number: FERRITE_SM-FB,120OHM,100MHZ,1.3A,A51464-017
J1 = CON2_HDR_SMT_0_1IN: part number: CON2_HDR_SMT_0_1IN_SM-EMPTY,SAMTEC,TSM-102-01-S-SV-P-TR,5P84X2P54MM,A79471-001
J2 J3 = CON100_RCPT: part number: CON100_RCPT_SM-CONN,HIROSE,DF40C-100DS-0.4V(51),,J22334-001
J4 = CON3_PWR_JACK_MTG2_TH: part number: CON3_PWR_JACK_MTG2_TH_THMT-CONN,CUI,PJ-041H,,J42411-001
J5 = CON8_MICROSD_MOLEX_503398: part number: CON8_MICROSD_MOLEX_503398_SM-CONN,MOLEX,503398-1892,13P5X14P35MM,G99936-001
J6 J8 = CON9_USB3_A_MTG4: part number: CON9_USB3_A_MTG4_THMT-CONN,MOLEX,048393-0003,,J41996-001
J7 = CON24_USB_TYPEC_8GND: part number: CON24_USB_TYPEC_8GND_SM-CONN,LOTES,AUSB0269-P004A,J10843-001
J9 = CON6: part number: CON6_SM-EMPTY,SAMTEC,TSM-106-01-L-SV,,C42183-003
J10 = 10029449_001RLF: part number: 10029449_001RLF_SMTCONN-CONN,FCI AMPHENOL,10029449-001RLF,D75006-001
J12 = CON40_RCPT_REVERSE: part number: CON40_RCPT_REVERSE_REV-CONN,SAMTEC,TLE-120-01-G-DV-A,,D46367-002
J13 = CON60_RCPT: part number: CON60_RCPT_SM-CONN,TE CONNECTIVITY,5177985-2,,D26946-006
J15 J16 J18 J19 = CONN_STDOFF_TH: part number: CONN_STDOFF_TH-PEM STNDOFF SMT 3.66 X 1.5MM M1.6X0.35 FEMALE,CONN,PENN ENGINEERING,YQSMTSO-51732-ET,3.66X1.5MM,J30246-001
J17 = CON3_MTG2: part number: CON3_MTG2_SM-CONN,TE,292228-3,J26417-001
J20 J21 = CON4_COAX_2X2_MM4829_2702: part number: CON4_COAX_2X2_MM4829_2702_SM-CONN,FOXCONN,KK12011-02-7H,2P2X2P2MM,G42632-004
J22 J23 = CABLE_HOLDER: part number: CABLE_HOLDER_SM-CONN,EMI STOP CORP,SV-08M,H12335-001
L2 = IND: part number: IND_0806-1.0UH,30%,1400MA,IND,652666-055; tolerance: 30%; room: NO_ROOM
L3 L4 L14 L15 = CHOKE_6PIN: part number: CHOKE_6PIN_0806-35OHM,,.1A,IND,752402-034; room: USB
L5 = IND: part number: IND_0806-1.0UH,30%,1400MA,IND,652666-055; tolerance: 30%
L6-L9 = CHOKE_6PIN: part number: CHOKE_6PIN_0806-35OHM,,.1A,IND,752402-034
L10 L11 L18-L20 = TCE1608G: part number: TCE1608G_1608-90OHM_100MHZ,,100MA,IND,752402-036
L21 U19 U20 = ECMF02_2BF3: part number: ECMF02_2BF3_BGA-IC,STMICRO,ECMF02-2BF3,G89122-001; room: USB
L22 L24 = IND: part number: IND_0402-1.3NH,,1.2A,IND,A47303-136
L23 = IND: part number: IND_0402-10NH,2%,100MA,IND,G87786-001; tolerance: 2%
L25 = IND: part number: IND_0402-2.2NH,9%,1A,IND,A47303-153; tolerance: 9%
L26 = IND: part number: IND_0402-2.7NH,0.2%,850MA,IND,A47303-173; tolerance: 0.2%
L27 = IND: part number: IND_0402-1.0NH,0.1%,400MA,IND,A47303-077; tolerance: 0.1%
L29 L30 = IND_ALTSIZE_TM: part number: IND_ALTSIZE_TM_7030-4.7UH,20%,6.9A,IND,J43094-001; tolerance: 20%
LB1 = LABEL_ASSEMBLY: part number: LABEL_ASSEMBLY-LABEL,SM,EMPTY
MT1-MT4 = MTG_HOLE_2P5MM_4_4: part number: MTG_HOLE_2P5MM_4_4-MTG_C10N98_197PAD,SM,EMPTY,REQ45454
Q1 = CSD17381F4: part number: CSD17381F4_DFN-FET-N,EMPTY,H31491-001; room: NO_ROOM
Q2 = CSD17381F4: part number: CSD17381F4_DFN-FET-N,XSTR,H31491-001; room: NO_ROOM
Q3 Q4 = MBT3904DUAL: part number: MBT3904DUAL_SOT363-NPN,XSTR,C52264-001
Q5 = FDMC013P030Z: part number: FDMC013P030Z_WPAK8-PCH,XSTR,J42149-001; room: NO_ROOM
R1 = RES_PMR_6TERM: part number: RES_PMR_6TERM_1206-0.01 OHM,1%,1W,CH,G52199-002; room: NO_ROOM
R2 R3 R9 R12 R15 R20 R35 R77 R79 R102 R132 = RES: part number: RES_0402-10K,5%,1/16W,CH,A93549-023
R4 = RES: part number: RES_0402-1.1K,1%,1/16W,CH,A93548-013; room: RTC_BAT
R5 R27 R34 = RES: part number: RES_0402-4.7K,5%,1/16W,CH,A93549-020
R7 R32 R33 R39 R52 R61 R73 R78 R100 R115 R120 R133 R137 R138 R141 R142 R146 = RES: part number: RES_0402-0,5%,1/16W,CH,A93549-001
R8 R68 = RES: part number: RES_0402-100K,5%,1/16W,EMPTY,A93549-027
R10 R11 R21 R22 = RES: part number: RES_0402-2.7K,5%,1/16W,CH,A93549-018; room: HDMI_MISC
R13 R14 R16-R19 R131 R134 = RES: part number: RES_0402-10K,5%,1/16W,EMPTY,A93549-023
R23 R45 R80 = RES: part number: RES_0402-37.4K,1%,1/16W,CH,A93548-190
R24 R81 = RES: part number: RES_0402-10K,1%,1/16W,CH,A93548-034
R25 = RES: part number: RES_0402-649K,1%,1/16W,EMPTY,A93548-540
R26 = RES: part number: RES_0402-130K,1%,1/16W,EMPTY,A93548-182
R28 R38 R41 R42 R63 R65 R103 R104 = RES: part number: RES_0402-4.7K,5%,1/16W,EMPTY,A93549-020
R29 = RES: part number: RES_0402-1M,5%,1/16W,CH,A93549-028
R30 = RES: part number: RES_0402-90.9K,1%,1/16W,CH,A93548-381
R31 R82 = RES: part number: RES_0402-1.87K,1%,1/16W,CH,A93548-445
R36 R46 R51 R57 R140 = RES: part number: RES_0402-100K,5%,1/16W,CH,A93549-027
R37 = RES: part number: RES_0402-4.99K,1%,1/16W,CH,A93548-202; room: NO_ROOM
R43 = RES: part number: RES_0603-9.53K,1%,1/10W,CH,A93550-414
R44 = RES: part number: RES_0402-237K,1%,1/16W,CH,A93548-545
R47 R48 = RES: part number: RES_0402-1.1K,1%,1/16W,CH,A93548-013; room: TEST_APE
R49 R50 = RES: part number: RES_0402-1.1K,1%,1/16W,CH,A93548-013; room: NO_ROOM
R53 = RES: part number: RES_0402-56.2K,1%,1/16W,CH,A93548-119
R54 R58 R62 = RES: part number: RES_0402-26.1K,1%,1/16W,CH,A93548-428
R55 = RES: part number: RES_0402-76.8K,1%,1/16W,CH,A93548-576
R56 = RES: part number: RES_0402-37.4K,1%,1/20W,CH,C48657-089
R64 R116 R124 = RES: part number: RES_0402-0,5%,1/16W,EMPTY,A93549-001
R66 = RES: part number: RES_1210-0,5%,1/2W,CH,A93552-007
R93-R96 = RES: part number: RES_0402-560,1%,1/16W,CH,A93548-461
R98 = RES: part number: RES_0402-100,5%,1/16W,CH,A93549-009
R136 = RES: part number: RES_0402-1.1K,1%,1/16W,CH,A93548-013
R143 = RES: part number: RES_0402-150K,1%,1/16W,CH,A93548-220
R145 = RES: part number: RES_0402-3.65K,1%,1/16W,CH,A93548-065
SW2 SW3 = SWITCH_SPST_4P: part number: SWITCH_SPST_4P_SM-SWITCH,E-SWITCH,TL3304AF160QJ,6.2X6.8MM,672681-002
TP1 = TESTPAD_SQ: part number: TESTPAD_SQ_SMT-S16,EMPTY; room: CWS_WLAN_BT
TP3-TP9 TP11-TP15 TP17 TP18 TP35 TP49 TP50 TP64 TP65 = TESTPAD_SQ: part number: TESTPAD_SQ_SMT-S16,EMPTY; room: NO_ROOM
TP16 TP19 TP20 = TESTPAD_SQ: part number: TESTPAD_SQ_SMT-S20,EMPTY
TP24 TP25 TP32 TP33 TP42 = TESTPAD_SQ: part number: TESTPAD_SQ_SMT-S16,EMPTY; room: USB
TP56 TP57 TP59 TP62 TP63 TP68 = TESTPAD_CIR: part number: TESTPAD_CIR_SMT-C40,EMPTY
U1 = IP4856CX25: part number: IP4856CX25_BGA-IC,NXP,IP4856CX25,H39559-001
U2 = TUSB8041: part number: TUSB8041_LCC-IC,TI,TUSB8041RGC,H94874-001; room: NO_ROOM
U3 = PS8203: part number: PS8203_LCC-IC,PARADE,PS8203TQFN32GTR-A3,H10648-003; room: HDMI_IC
U4 = ECMF02_2BF3: part number: ECMF02_2BF3_BGA-IC,STMICRO,ECMF02-2BF3,G89122-001
U5 U27 = TLV62084: part number: TLV62084_LCC-IC,TI,TLV62084DSGR,H65953-001
U6 = PI3USB302_A: part number: PI3USB302_A_LCC-IC,PERICOM,PI3USB302-A,H35999-001; room: USB
U14 = M24M02_DR: part number: M24M02_DR_SOIC-IC,ST,M24M02-DRMN6TP,H59083-001; room: NO_ROOM
U15 U16 = TPS2553: part number: TPS2553_LCC-IC,TI,TPS2553DRVT,G19844-001; room: USB
U17 U22 U26 = TPS2553: part number: TPS2553_LCC-IC,TI,TPS2553DRVT,G19844-001
U18 U21 = TPS54531: part number: TPS54531_SOIC-IC,TI,TPS54531,J17247-001
U24 = FPF2195: part number: FPF2195_CSP-IC,FAIRCHILD,FPF2195,H55117-001
Y1 = XTAL_4PIN: part number: XTAL_4PIN_SM-24.00MHZ,+/-30PPM,18PF,XTAL,D71700-052

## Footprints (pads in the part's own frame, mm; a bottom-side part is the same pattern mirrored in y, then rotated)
1X6_P100IN_SM_HDR
  rect 1.27x3.429 smd: 1(-6.35,1.46) 2(-3.81,-1.46) 3(-1.27,1.46) 4(1.27,-1.46) 5(3.81,1.46) 6(6.35,-1.46)
2D_ID_TARGET_7P5X7P5MM_NOSM
  round 0 smd: 1(0,0)
2X20_2MM_3P98X40_RCPT_REV
  round 0.254 hole 0.762 unplated: (-18,0) (18,0)
  rect 1.12x2.105 smd: 1(-19,-2.223) 2(-19,2.223) 3(-17,-2.223) 4(-17,2.223) 5(-15,-2.223) 6(-15,2.223) 7(-13,-2.223) 8(-13,2.223) 9(-11,-2.223) 10(-11,2.223) 11(-9,-2.223) 12(-9,2.223) 13(-7,-2.223) 14(-7,2.223) 15(-5,-2.223) 16(-5,2.223) 17(-3,-2.223) 18(-3,2.223) 19(-1,-2.223) 20(-1,2.223) 21(1,-2.223) 22(1,2.223) 23(3,-2.223) 24(3,2.223) 25(5,-2.223) 26(5,2.223) 27(7,-2.223) 28(7,2.223) 29(9,-2.223) 30(9,2.223) 31(11,-2.223) 32(11,2.223) 33(13,-2.223) 34(13,2.223) 35(15,-2.223) 36(15,2.223) 37(17,-2.223) 38(17,2.223) 39(19,-2.223) 40(19,2.223)
2X30_P8MM_BTB_RCPT_VT_4P0H
  round 0.508 hole 1.2 unplated: (-14.1,0)
  round 0.508 hole 0.8 unplated: (14.1,0)
  rect 0.5x2 smd: 1(-11.6,-2.2) 2(-11.6,2.2) 3(-10.8,-2.2) 4(-10.8,2.2) 5(-10,-2.2) 6(-10,2.2) 7(-9.2,-2.2) 8(-9.2,2.2) 9(-8.4,-2.2) 10(-8.4,2.2) 11(-7.6,-2.2) 12(-7.6,2.2) 13(-6.8,-2.2) 14(-6.8,2.2) 15(-6,-2.2) 16(-6,2.2) 17(-5.2,-2.2) 18(-5.2,2.2) 19(-4.4,-2.2) 20(-4.4,2.2) 21(-3.6,-2.2) 22(-3.6,2.2) 23(-2.8,-2.2) 24(-2.8,2.2) 25(-2,-2.2) 26(-2,2.2) 27(-1.2,-2.2) 28(-1.2,2.2) 29(-0.4,-2.2) 30(-0.4,2.2) 31(0.4,-2.2) 32(0.4,2.2) 33(1.2,-2.2) 34(1.2,2.2) 35(2,-2.2) 36(2,2.2) 37(2.8,-2.2) 38(2.8,2.2) 39(3.6,-2.2) 40(3.6,2.2) 41(4.4,-2.2) 42(4.4,2.2) 43(5.2,-2.2) 44(5.2,2.2) 45(6,-2.2) 46(6,2.2) 47(6.8,-2.2) 48(6.8,2.2) 49(7.6,-2.2) 50(7.6,2.2) 51(8.4,-2.2) 52(8.4,2.2) 53(9.2,-2.2) 54(9.2,2.2) 55(10,-2.2) 56(10,2.2) 57(10.8,-2.2) 58(10.8,2.2) 59(11.6,-2.2) 60(11.6,2.2)
2X50_P4MM_1P6H_BTB_RCPT_DF40C
  rect 0.2x0.7 smd: 1(0,0) 2(0,-3.08) 3(0.4,0) 4(0.4,-3.08) 5(0.8,0) 6(0.8,-3.08) 7(1.2,0) 8(1.2,-3.08) 9(1.6,0) 10(1.6,-3.08) 11(2,0) 12(2,-3.08) 13(2.4,0) 14(2.4,-3.08) 15(2.8,0) 16(2.8,-3.08) 17(3.2,0) 18(3.2,-3.08) 19(3.6,0) 20(3.6,-3.08) 21(4,0) 22(4,-3.08) 23(4.4,0) 24(4.4,-3.08) 25(4.8,0) 26(4.8,-3.08) 27(5.2,0) 28(5.2,-3.08) 29(5.6,0) 30(5.6,-3.08) 31(6,0) 32(6,-3.08) 33(6.4,0) 34(6.4,-3.08) 35(6.8,0) 36(6.8,-3.08) 37(7.2,0) 38(7.2,-3.08) 39(7.6,0) 40(7.6,-3.08) 41(8,0) 42(8,-3.08) 43(8.4,0) 44(8.4,-3.08) 45(8.8,0) 46(8.8,-3.08) 47(9.2,0) 48(9.2,-3.08) 49(9.6,0) 50(9.6,-3.08) 51(10,0) 52(10,-3.08) 53(10.4,0) 54(10.4,-3.08) 55(10.8,0) 56(10.8,-3.08) 57(11.2,0) 58(11.2,-3.08) 59(11.6,0) 60(11.6,-3.08) 61(12,0) 62(12,-3.08) 63(12.4,0) 64(12.4,-3.08) 65(12.8,0) 66(12.8,-3.08) 67(13.2,0) 68(13.2,-3.08) 69(13.6,0) 70(13.6,-3.08) 71(14,0) 72(14,-3.08) 73(14.4,0) 74(14.4,-3.08) 75(14.8,0) 76(14.8,-3.08) 77(15.2,0) 78(15.2,-3.08) 79(15.6,0) 80(15.6,-3.08) 81(16,0) 82(16,-3.08) 83(16.4,0) 84(16.4,-3.08) 85(16.8,0) 86(16.8,-3.08) 87(17.2,0) 88(17.2,-3.08) 89(17.6,0) 90(17.6,-3.08) 91(18,0) 92(18,-3.08) 93(18.4,0) 94(18.4,-3.08) 95(18.8,0) 96(18.8,-3.08) 97(19.2,0) 98(19.2,-3.08) 99(19.6,0) 100(19.6,-3.08)
672681-002
  rect 3.302x0.991 smd: 1(0,0) 2(6.299,0) 3(0,-4.013) 4(6.299,-4.013)
A79471-001
  rect 3.429x1.27 smd: 1(0,0) 2(-2.921,-2.54)
BATT_HLDR_3P_13P5X9P5MM
  rect 2.5x5.1 smd: 1(0,0) 2(15.3,0)
  round 10.2 smd: 3(7.65,0.05)
BGA4_FLIPCHIP
  round 0.229 smd: A1(0,0) A2(0.401,0) B1(0,-0.401) B2(0.401,-0.4)
BGA5_P4MM_1P27XP86MM
  round 0.25 smd: A1(-0.2,0.4) A2(0.2,0.4) B1(-0.2,0) B2(0.2,0) C2(0.2,-0.4)
BGA25_P4MM_2P06SQ_P5H
  round 0.25 smd: A1(-0.8,0.8) A2(-0.4,0.8) A3(0,0.8) A4(0.4,0.8) A5(0.8,0.8) B1(-0.8,0.4) B2(-0.4,0.4) B3(0,0.4) B4(0.4,0.4) B5(0.8,0.4) C1(-0.8,0) C2(-0.4,0) C3(0,0) C4(0.4,0) C5(0.8,0) D1(-0.8,-0.4) D2(-0.4,-0.4) D3(0,-0.4) D4(0.4,-0.4) D5(0.8,-0.4) E1(-0.8,-0.8) E2(-0.4,-0.8) E3(0,-0.8) E4(0.4,-0.8) E5(0.8,-0.8)
CABLE_HOLDER_SV08M
  custom 0.275x0.275 smd: 1(0,0)
CON3_1P5MM_4P9H_SM_MINI_CT
  rect 0.9x3.3 smd: 1(0,0) 2(1.5,0) 3(3,0)
  rect 2.4x3.3 smd: 4(-3.5,-5) 5(6.5,-5)
CON8_1P1MM_SD503398_MOLEX
  rect 0.7x1.1 smd: 1(0,0) 2(1.1,0) 3(2.2,0) 4(3.3,0) 5(4.4,0) 6(5.5,0) 7(6.6,0) 8(7.7,0)
  rect 0.9x0.93 smd: 9(-1.79,-12.465)
  rect 1.05x0.78 smd: 10(2.475,-12.54)
  rect 0.7x3.33 smd: 11(-4.1,-11.265) 12(8.86,-11.265)
  rect 1.14x1.83 smd: 13(-3.88,-0.015)
  rect 0.86x2.8 smd: 14(8.78,-0.5)
CON9_USB3_RA_TH_6P86H
  round 1.092 hole 0.711: 1(-3.5,-0.5) 2(-1,-0.5) 3(1,-0.5) 4(3.5,-0.5) 5(4,1) 6(2,1) 7(0,1) 8(-2,1) 9(-4,1)
  oval 1.397x2.489 hole 0.61x1.702: 10(-6.4,0.25) 11(6.4,0.25)
  oval 1.499x2.362 hole 0.61x1.448: 12(-6.4,-8.25) 13(6.4,-8.25)
CON19_P5MM_HDMI_MALE_RA_SM_6P3H
  rect 0.3x1.9 smd: 1(4.75,5.8) 2(4.25,5.8) 3(3.75,5.8) 4(3.25,5.8) 5(2.75,5.8) 6(2.25,5.8) 7(1.75,5.8) 8(1.25,5.8) 9(0.75,5.8) 10(0.25,5.8) 11(-0.25,5.8) 12(-0.75,5.8) 13(-1.25,5.8) 14(-1.75,5.8) 15(-2.25,5.8) 16(-2.75,5.8) 17(-3.25,5.8) 18(-3.75,5.8) 19(-4.25,5.8)
  oval 1.2x2.5 hole 0.61x1.905: 20(-7.25,4.9) 21(-7.85,0) 22(7.85,0) 23(7.25,4.9)
CON24_USB_C_HYBRID_10P15X11P35
  round 0.254 hole 0.66 unplated: (-3.6,0)
  oval 0.406x0.254 hole 0.965x0.66 unplated: (3.6,0)
  rect 0.3x0.9 smd: A1(-2.75,0.56) A2(-2.25,0.56) A3(-1.75,0.56) A4(-1.25,0.56) A5(-0.75,0.56) A6(-0.25,0.56) A7(0.25,0.56) A8(0.75,0.56) A9(1.25,0.56) A10(1.75,0.56) A11(2.25,0.56) A12(2.75,0.56)
  round 0.66 hole 0.406: B1(2.8,-0.65) B2(2.4,-1.35) B3(1.6,-1.35) B4(1.2,-0.65) B5(0.8,-1.35) B6(0.4,-0.65) B7(-0.4,-0.65) B8(-0.8,-1.35) B9(-1.2,-0.65) B10(-1.6,-1.35) B11(-2.4,-1.35) B12(-2.8,-0.65)
  oval 0.991x1.905 hole 0.508x1.397: M1(-4.6,-1.25) M2(4.6,-1.25)
  oval 0.991x2.108 hole 0.508x1.6: M3(-4.6,-4.45) M4(4.6,-4.45)
  rect 0.5x0.3 smd: M5(-3.37,1.55) M6(-1.25,1.55) M7(1.25,1.55) M8(3.38,1.55)
CONN_COAX_SMT_2X2
  rect 0.61x0.559 smd: 1(0,-0.979)
  rect 0.508x0.508 smd: 2(0,1.016)
  rect 0.584x1.575 smd: 3(-0.965,0) 4(0.965,0)
CSP6_P5MM_1P55X1P05
  round 0.25 smd: A1(-0.25,0.5) A2(0.25,0.5) B1(-0.25,0) B2(0.25,0) C1(-0.25,-0.5) C2(0.25,-0.5)
DC_PWR_JACK_1P65X5P15MM_RA_TH
  round 0.254 hole 1.3 unplated: (-7.9,2.5) (-7.9,-1.5)
  oval 1.981x1.181 hole 1.6x0.8: 1(0,0) 2(-2.9,3.4) 3(0,3.4)
DO214AB
  rect 2.6x3.2 smd: 1(-3.6,0) 2(3.6,0)
LCC6_P65MM_2P1X2P1_EP1P0X1P6
  rect 0.5x0.3 smd: 1(0,0) 2(0,-0.65) 3(0,-1.3) 4(2,-1.3) 5(2,-0.65) 6(2,0)
  rect 1x1.6 smd: 7(1,-0.65)
LCC8_P5MM_2P1SQ_EP1P6XP9
  rect 0.25x0.375 smd: 1(-0.75,-0.887) 2(-0.25,-0.887) 3(0.25,-0.887) 4(0.75,-0.887) 5(0.75,0.887) 6(0.25,0.887) 7(-0.25,0.887) 8(-0.75,0.887)
  rect 1.6x0.9 smd: 9(0,0)
LCC10_P4MM_1608
  rect 0.47x0.2 smd: 1(0,0) 2(0,-0.4) 3(0,-0.8) 4(0,-1.2) 5(0.95,-1.2) 6(0.95,-0.8) 7(0.95,-0.4) 8(0.95,0)
  rect 0.15x0.35 smd: 9(0.475,0.225) 10(0.475,-1.425)
LCC20_P5MM_2P5X4P5_EP1X3
  rect 0.25x0.475 smd: 1(-0.25,2.087) 10(-0.25,-2.087) 11(0.25,-2.087) 20(0.25,2.087)
  rect 0.475x0.25 smd: 2(-1.087,1.75) 3(-1.087,1.25) 4(-1.087,0.75) 5(-1.087,0.25) 6(-1.087,-0.25) 7(-1.087,-0.75) 8(-1.087,-1.25) 9(-1.087,-1.75) 12(1.087,-1.75) 13(1.087,-1.25) 14(1.087,-0.75) 15(1.087,-0.25) 16(1.087,0.25) 17(1.087,0.75) 18(1.087,1.25) 19(1.087,1.75)
  rect 1x3 smd: 21(0,0)
LCC32_P4MM_6X3_P8H
  rect 0.425x0.2 smd: 1(-1.363,2) 2(-1.363,1.6) 3(-1.363,1.2) 4(-1.363,0.8) 5(-1.363,0.4) 6(-1.363,0) 7(-1.363,-0.4) 8(-1.363,-0.8) 9(-1.363,-1.2) 10(-1.363,-1.6) 11(-1.363,-2) 17(1.363,-2) 18(1.363,-1.6) 19(1.363,-1.2) 20(1.363,-0.8) 21(1.363,-0.4) 22(1.363,0) 23(1.363,0.4) 24(1.363,0.8) 25(1.363,1.2) 26(1.363,1.6) 27(1.363,2)
  rect 0.2x0.425 smd: 12(-0.8,-2.863) 13(-0.4,-2.863) 14(0,-2.863) 15(0.4,-2.863) 16(0.8,-2.863) 28(0.8,2.863) 29(0.4,2.863) 30(0,2.863) 31(-0.4,2.863) 32(-0.8,2.863)
  rect 1.8x4.6 smd: 33(0,0)
LCC64_P5MM_9SQ_EP6P0
  rect 0.475x0.25 smd: 1(-4.338,3.75) 2(-4.338,3.25) 3(-4.338,2.75) 4(-4.338,2.25) 5(-4.338,1.75) 6(-4.338,1.25) 7(-4.338,0.75) 8(-4.338,0.25) 9(-4.338,-0.25) 10(-4.338,-0.75) 11(-4.338,-1.25) 12(-4.338,-1.75) 13(-4.338,-2.25) 14(-4.338,-2.75) 15(-4.338,-3.25) 16(-4.338,-3.75) 33(4.338,-3.75) 34(4.338,-3.25) 35(4.338,-2.75) 36(4.338,-2.25) 37(4.338,-1.75) 38(4.338,-1.25) 39(4.338,-0.75) 40(4.338,-0.25) 41(4.338,0.25) 42(4.338,0.75) 43(4.338,1.25) 44(4.338,1.75) 45(4.338,2.25) 46(4.338,2.75) 47(4.338,3.25) 48(4.338,3.75)
  rect 0.25x0.475 smd: 17(-3.75,-4.338) 18(-3.25,-4.338) 19(-2.75,-4.338) 20(-2.25,-4.338) 21(-1.75,-4.338) 22(-1.25,-4.338) 23(-0.75,-4.338) 24(-0.25,-4.338) 25(0.25,-4.338) 26(0.75,-4.338) 27(1.25,-4.338) 28(1.75,-4.338) 29(2.25,-4.338) 30(2.75,-4.338) 31(3.25,-4.338) 32(3.75,-4.338) 49(3.75,4.338) 50(3.25,4.338) 51(2.75,4.338) 52(2.25,4.338) 53(1.75,4.338) 54(1.25,4.338) 55(0.75,4.338) 56(0.25,4.338) 57(-0.25,4.338) 58(-0.75,4.338) 59(-1.25,4.338) 60(-1.75,4.338) 61(-2.25,4.338) 62(-2.75,4.338) 63(-3.25,4.338) 64(-3.75,4.338)
  rect 6x6 smd: 65(0,0)
MTG_C10N98_197PAD
  round 0.254 hole 2.489 unplated: (0,0)
  custom 0.6x0.6 smd: 1(1.31,1.274) 2(-1.28,1.32) 3(-1.32,-1.29) 4(1.27,-1.33)
  custom 0.599x0.599 smd: 5(1.33,1.25) 6(-1.24,1.33) 7(-1.33,-1.25) 8(1.24,-1.34)
PEM_NUT_2P31_3P66MM_1P5H
  round 2.997 hole 2.591: 1(0,0)
SM_3P_0P6X1P0
  rect 0.15x0.25 smd: 1(0,0) 2(0.35,0)
  rect 0.5x0.25 smd: 3(0.175,0.65)
SMC0201
  custom 0.062x0.062 smd: 1(0,0) 2(0,-0.451)
SMC0402
  custom 0.096x0.096 smd: 1(0,0) 2(0,-0.766)
SMC0603
  custom 0.174x0.174 smd: 1(0,0) 2(0,-1.204)
SMC0603_67X35_42H
  custom 0.191x0.191 smd: 1(0,0) 2(0,-1.397)
SMC0805_1P4H
  custom 0.205x0.205 smd: 1(0,0) 2(0,-1.581)
SMC0805_1P45H
  custom 0.205x0.205 smd: 1(0,0) 2(0,-1.581)
SMC1206_1P8W_1P8H
  custom 0.254x0.254 smd: 1(0,1.397) 2(0,-1.397)
SMC1210
  rect 2.54x1.905 smd: 1(0,0) 2(0,-3.683)
SMCR0201
  custom 0.062x0.062 smd: 1(0,0) 2(0,-0.451)
SMCR_0P85X1P25_P65H
  rect 0.35x0.475 smd: 1(0,0.688) 2(0,-0.688)
SMF0402
  custom 0.096x0.096 smd: 1(0,0) 2(0,-0.766)
SMF0603
  custom 0.174x0.174 smd: 1(0,0) 2(0,-1.204)
SMFUSE0402_P432H
  custom 0.096x0.096 smd: 1(0,0) 2(0,-0.766)
SMFUSE1206_34H
  rect 1.016x1.803 smd: 1(0,0) 2(2.819,0)
SMFUSE1206_39H
  rect 1.016x1.803 smd: 1(0,0) 2(2.819,0)
SML0402
  custom 0.096x0.096 smd: 1(0,0) 2(0,-0.766)
SML0806
  rect 1.778x1.016 smd: 1(0,0.724) 2(0,-0.724)
SML_6P_0P65X0P85
  custom 0.052x0.052 smd: 1(0,0) 2(0.51,0) 3(0.51,-0.647) 4(0,-0.647)
  custom 0.039x0.039 smd: 5(-0.178,-0.324) 6(0.69,-0.324)
SML_40X24
  custom 0.127x0.127 smd: 1(0,0) 2(0,-0.889)
SML_SQ7P5_3P1H
  rect 1.78x6.5 smd: 1(-2.36,0) 2(2.36,0)
SMLED0603
  custom 0.174x0.174 smd: 1(0,0) 2(0,-1.204)
SMR0402
  custom 0.096x0.096 smd: 1(0,0) 2(0,-0.766)
SMR0402_16H
  custom 0.096x0.096 smd: 1(0,0.383) 2(0,-0.383)
SMR0603
  custom 0.174x0.174 smd: 1(0,0) 2(0,-1.204)
SMR1206_SNS_B
  rect 0.61x1.575 smd: 1(0.584,-0.229) 3(-0.584,-0.229) 4(-0.584,-2.565) 6(0.584,-2.565)
  rect 0.254x1.575 smd: 2(0,-0.229) 5(0,-2.565)
SMR1210
  rect 2.54x1.524 smd: 1(0,0) 2(0,-3.302)
SMY_4P_98X126_32H
  rect 1.194x1.397 smd: 1(0,0) 2(0,-2.2) 3(1.6,-2.2) 4(1.6,0)
SOD123W
  rect 1.2x1.2 smd: 1(0,1.4) 2(0,-1.4)
SOD323
  rect 0.508x1.016 smd: 1(0,0) 2(0,-2.54)
SOI8_1P27_5X4MM_EP2P4X3P05_1P7H
  rect 2x0.52 smd: 1(-2.7,1.905) 2(-2.7,0.635) 3(-2.7,-0.635) 4(-2.7,-1.905) 5(2.7,-1.905) 6(2.7,-0.635) 7(2.7,0.635) 8(2.7,1.905)
  rect 2.4x3.05 smd: 9(0,0)
SOI8_50IN_157X197
  rect 2.286x0.635 smd: 1(0.457,0) 2(0.457,-1.27) 3(0.457,-2.54) 4(0.457,-3.81) 5(5.029,-3.81) 6(5.029,-2.54) 7(5.029,-1.27) 8(5.029,0)
SOT363
  rect 1.016x0.381 smd: 1(0,0) 2(0,-0.65) 3(0,-1.3) 4(1.778,-1.3) 5(1.778,-0.65) 6(1.778,0)
TEST_SP_C10SM13
  round 0.254 smd: 1(0,0)
TESTPAD_C40
  round 1.016 smd: 1(0,0)
TESTPAD_S16
  rect 0.406x0.406 smd: 1(0,0)
TESTPAD_S20
  rect 0.508x0.508 smd: 1(0,0)
unnamed#2
  round 1.016 smd: (0,0)
unnamed#3
  round 0 smd: 1(0,0)
unnamed#4
  round 0 smd: 1(0.02,0.198)
WPAK8_3P3MMSQ_P8H
  rect 0.432x0.711 smd: 1(0,0) 2(0.65,0) 3(1.3,0) 4(1.95,0) 5(1.95,2.946) 6(1.3,2.946) 7(0.65,2.946) 8(0,2.946)
  rect 2.413x1.6 smd: 9(0.988,1.664)

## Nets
+5VP0V_HDMI_CONN: C11.1(A<0>) CR28.A1(CATHODE1) CR28.A2(CATHODE2) FB10.2(B) J10.18(+5V)
+5VP0V_HDMI_OUT_FILT: C15.1(A<0>) C82.1(A<0>) FB10.1(A) U26.1(OUT)
+V1P1V: C18.1(A<0>) C72.1(A<0>) FB6.1(A) L5.2(B) R53.1(A<0>) R57.1(A<0>) U5.5(VOS)
+V1P1V_USB_HUB: C23.1(A<0>) C25.1(A<0>) C33.1(A<0>) C38.1(A<0>) C56.1(A<0>) C57.1(A<0>) C58.1(A<0>) C61.1(A<0>) FB6.2(B) U2.5(VDD_1) U2.8(VDD_2) U2.13(VDD_3) U2.21(VDD_4) U2.28(VDD_5) U2.31(VDD_6) U2.51(VDD_7) U2.57(VDD_8)
+V1P8V: C5.1(A<0>) C105.1(A<0>) C124.1(A<0>) C140.1(A<0>) C143.1(A<0>) FB1.1(A) FB11.2(B) R8.1(A<0>) R9.1(A<0>) R10.1(A<0>) R11.1(A<0>) R98.1(A<0>) R131.1(A<0>) R133.1(A<0>) R134.1(A<0>) R136.1(A<0>) R138.1(A<0>) U3.30(VDDIO) U24.B2(VIN)
+V1P8V_MICROSD: C6.1(A<0>) FB1.2(B) U1.B3(VCCA)
+V3P3V: C4.1(A<0>) C10.1(A<0>) C27.1(A<0>) C34.1(A<0>) C69.1(A<0>) FB2.1(A) FB3.1(A) L2.2(B) R12.1(A<0>) R13.1(A<0>) R15.1(A<0>) R17.1(A<0>) R19.1(A<0>) R44.1(A<0>) R46.1(A<0>) R73.1(A<0>) U3.11(VDD) U27.5(VOS)
+V3P3V_MICROSD: C28.1(A<0>) CR7.1(PIN1) FB2.2(B) J5.4(VDD) U1.A4(VSUPPLY) U1.C4(VSD_REF)
+V3P3V_SW: L2.1(A) U27.7(SW)
+V3P3V_USB_HUB: C22.1(A<0>) C24.1(A<0>) C26.1(A<0>) C37.1(A<0>) C55.1(A<0>) FB3.2(B) R2.1(A<0>) R3.1(A<0>) R28.1(A<0>) R38.1(A<0>) R63.1(A<0>) U2.16(VDD33_1) U2.34(VDD33_2) U2.52(VDD33_3) U2.63(VDD33_4)
+V5P0V: C9.1(A<0>) C29.1(A<0>) C32.1(A<0>) C35.1(A<0>) C36.1(A<0>) C68.1(A<0>) C70.1(A<0>) C71.1(A<0>) C81.1(A<0>) C96.1(A<0>) C100.1(A<0>) C106.1(A<0>) C152.1(A<0>) C153.1(A<0>) CR4.2(A) CR5.2(A) F5.1 J17.1 L30.2 R30.1(A<0>) R34.1(A<0>) R52.1(A<0>) R81.1(A<0>) R93.1(A<0>) R94.1(A<0>) R95.1(A<0>) R96.1(A<0>) R140.1(A<0>) U5.8(VIN) U15.6(IN) U16.6(IN) U17.6(IN) U22.6(IN) U26.6(IN) U27.8(VIN)
+V5P0V_BREAKOUT: C53.1(A<0>) CR1.1(PIN1) F5.2 J12.37
+V5P0V_USBA_1: C30.1(A<0>) C31.1(A<0>) C130.1(A<0>) C161.1(A<0>) FB7.1(A) U15.1(OUT)
+V5P0V_USBA_2: C97.1(A<0>) C98.1(A<0>) C131.1(A<0>) C162.1(A<0>) FB8.1(A) U16.1(OUT)
+V5P0V_VCONN: C60.1(A<0>) C126.1(A<0>) J2.41 U17.1(OUT)
+VBUS: C59.1(A<0>) C62.1(A<0>) C127.1(A<0>) FB9.1(A) J2.99 U22.1(OUT)
+VBUS_USBC: F2.2 J7.A4 J7.A9 J7.B4 J7.B9
+VBUS_USBC_F: C63.1(A<0>) CR10.A1(CATHODE1) CR10.A2(CATHODE2) F2.1 FB9.2(B)
+VDD1: C123.1(A<0>) FB11.1(A) J2.36
+VDD3: C122.1(A<0>) J2.30 R78.1(A<0>)
+VDD_USBC_MUX: C65.1(A<0>) C66.1(A<0>) C67.1(A<0>) R73.2(B<0>) U6.1(VDD_1) U6.6(VDD_2) U6.10(VDD_3)
